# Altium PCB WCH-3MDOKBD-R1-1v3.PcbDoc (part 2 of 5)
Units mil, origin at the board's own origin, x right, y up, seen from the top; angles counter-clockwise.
Board outline 11710.74 x 4477.49 mil, 2 copper layers (Top Layer, Bottom Layer); 422 components, 246 nets, 927 pads, 1295 vias.
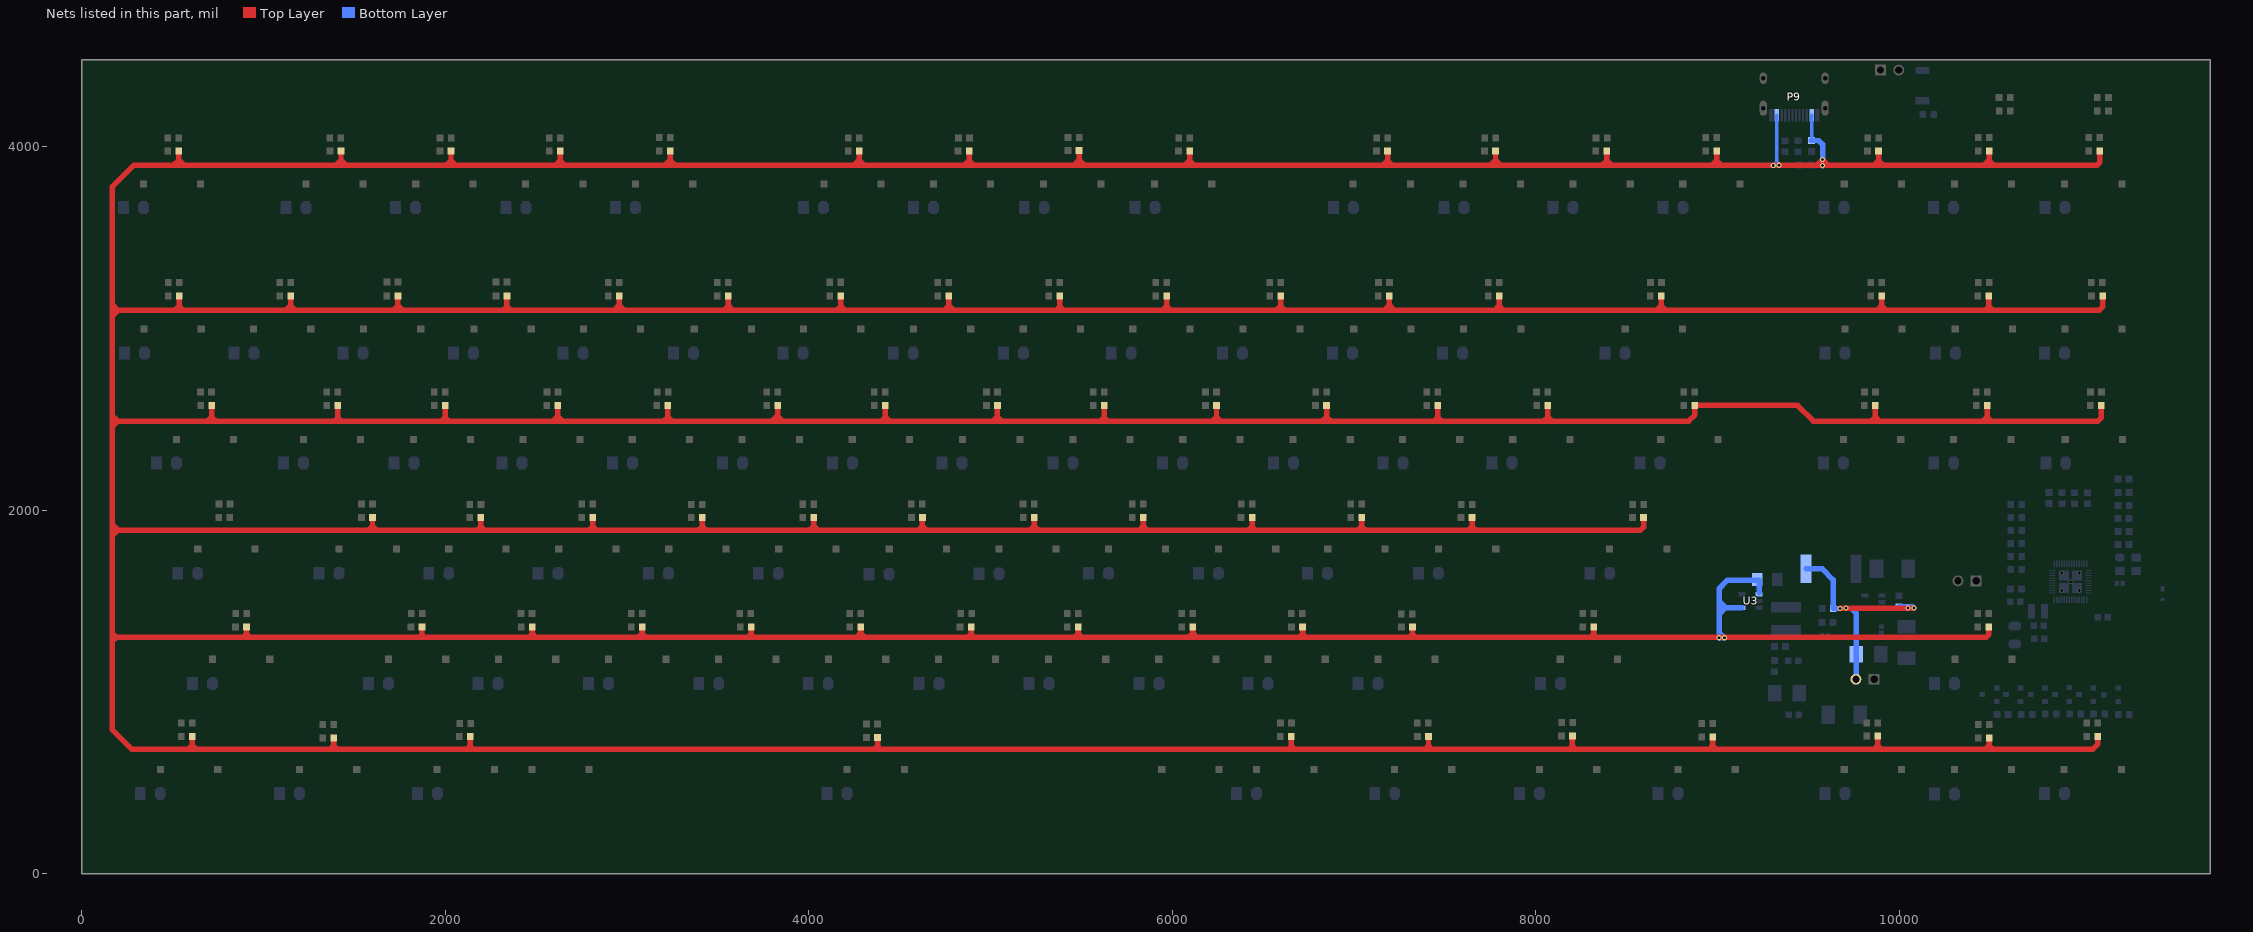
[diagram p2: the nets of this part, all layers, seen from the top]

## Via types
v1: diameter 28, hole 16, Top Layer to Bottom Layer, tented both sides, 1167 vias
v2: diameter 24, hole 12, Top Layer to Bottom Layer, tented both sides, 128 vias

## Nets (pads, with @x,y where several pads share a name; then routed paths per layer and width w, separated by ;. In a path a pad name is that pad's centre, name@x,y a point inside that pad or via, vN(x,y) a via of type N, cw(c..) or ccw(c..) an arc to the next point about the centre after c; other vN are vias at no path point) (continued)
+5V: C13.1 D199.A D227.A D228.A D229.A LD7.A LD8.A LD9.A LD10.A LD11.A LD12.A LD13.A LD14.A LD15.A LD16.A LD17.A LD18.A LD19.A LD21.A LD22.A LD23.A LD52.A LD53.A LD54.A LD55.A LD56.A LD57.A LD58.A LD59.A LD60.A LD61.A LD62.A LD63.A LD64.A LD65.A LD66.A LD67.A LD68.A LD93.A LD94.A LD95.A LD96.A LD97.A LD98.A LD99.A LD100.A LD101.A LD102.A LD103.A LD104.A LD105.A LD106.A LD107.A LD108.A LD109.A LD140.A LD141.A LD142.A LD143.A LD144.A LD145.A LD146.A LD147.A LD148.A LD149.A LD150.A LD151.A LD186.A LD187.A LD188.A LD189.A LD190.A LD191.A LD192.A LD193.A LD194.A LD195.A LD196.A LD197.A LD216.A LD217.A LD218.A LD219.A LD220.A LD223.A LD224.A LD_Fn.A P9.A4 P9.B4 R120.2 U3.1 U3.4 | length 79078.6
  Top Layer w30: 181.93,1299.88 191.02,1299.88 ; 535.31,3902.68 535.31,3926.41 ; LD7.A@535.31,3974.68 535.31,3926.41 ; 536.96,3103.97 536.96,3123.41 ; LD52.A@536.96,3178.04 536.96,3123.41 ; LD216.A@609.65,754.02 609.65,707.07 ; LD93.A@715.77,2575.56 715.77,2511.81 ; LD186.A@907.17,1355.98 907.17,1319.78 ; LD53.A@1149.98,3178.04 1149.98,3125.55 ; LD217.A@1386.96,745.9 1386.96,703.42 ; LD94.A@1409.4,2575.56 1409.4,2506.45 ; LD8.A@1427.03,3974.68 1427.03,3924.64 ; LD140.A@1600.46,1958.93 1600.46,1911.21 ; LD54.A@1740.36,3178.04 1740.36,3125.91 ; LD187.A@1872.66,1355.98 1872.66,1316.44 ; LD95.A@2000.22,2575.56 2000.22,2509.1 ; LD9.A@2032.19,3974.68 2032.19,3922.79 ; LD218.A@2137.51,752.89 2137.51,700.94 ; LD141.A@2196.21,1958.93 2196.21,1908.98 ; LD55.A@2340.06,3178.04 2340.06,3119.75 ; LD188.A@2479.54,1355.98 2479.54,1320.12 ; LD96.A@2619.91,2575.56 2619.91,2516.11 ; LD10.A@2632.59,3974.68 2632.59,3921.47 ; LD142.A@2812.52,1958.93 2812.52,1910.44 ; LD56.A@2957.21,3178.04 2957.21,3127.09 ; LD189.A@3083.53,1355.98 3083.53,1321.18 ; LD97.A@3225.26,2575.56 3225.26,2511.9 ; LD11.A@3237.89,3974.68 3237.89,3925.14 ; LD143.A@3415,1958.93 3415,1909.78 ; LD57.A@3558.21,3178.04 3558.21,3123.97 ; LD190.A@3683.34,1355.98 3683.34,1316.71 ; LD98.A@3829.13,2575.56 3829.13,2519.76 ; LD144.A@4028.25,1960.07 4028.25,1912.17 ; LD58.A@4176.71,3178.04 4176.71,3122.1 ; LD12.A@4277.28,3974.68 4277.28,3924.46 ; LD191.A@4285.49,1355.98 4285.49,1323.43 ; LD219.A@4378.55,749.84 4378.55,702.7 ; LD99.A@4421.3,2575.56 4421.3,2510.41 ; LD145.A@4625.6,1959.98 4625.6,1911.6 ; LD59.A@4770.9,3178.04 4770.9,3126.34 ; LD13.A@4882.15,3974.68 4882.15,3922.76 ; LD192.A@4893.21,1355.98 4893.21,1318.91 ; LD100.A@5038.34,2575.56 5038.34,2513.17 ; LD146.A@5240.62,1960.08 5240.62,1911.5 ; LD60.A@5381.34,3178.04 5381.34,3120.73 ; LD193.A@5483.57,1355.98 5483.57,1320.74 ; LD14.A@5487.13,3977.21 5487.13,3926.34 ; LD101.A@5625.34,2575.56 5625.34,2509.61 ; LD147.A@5840.25,1958.93 5840.25,1911.44 ; LD61.A@5969.32,3178.04 5969.32,3122.21 ; LD15.A@6095.17,3974.68 6095.17,3921.75 ; LD194.A@6112.64,1355.98 6112.64,1323.51 ; LD102.A@6243.24,2575.56 6243.24,2511.86 ; LD148.A@6439,1958.93 6439,1909.1 ; LD62.A@6596.2,3178.04 6596.2,3123.43 ; LD220.A@6654.88,754.78 6654.88,702.72 ; LD195.A@6716.61,1355.98 6716.61,1318.53 ; LD103.A@6848.51,2575.56 6848.51,2512.65 ; LD149.A@7041.77,1958.93 7041.77,1909.7 ; LD16.A@7184.25,3974.68 7184.25,3921.68 ; LD63.A@7194.09,3178.04 7194.09,3126.97 ; LD196.A@7321.33,1355.98 7321.33,1317.87 ; LD_Fn.A@7409.48,754.78 7409.48,703.67 ; LD104.A@7460.26,2575.56 7460.26,2509.99 ; LD150.A@7648.87,1958.93 7648.87,1910.06 ; LD17.A@7778.06,3974.68 7778.06,3924.89 ; LD64.A@7798.02,3178.04 7798.02,3123.86 ; LD105.A@8065.67,2575.56 8065.67,2512.12 ; LD223.A@8201.34,756.15 8201.34,702.08 ; LD197.A@8317.72,1355.98 8317.72,1316.77 ; LD18.A@8390.67,3974.68 8390.67,3924.07 ; LD151.A@8592.3,1958.93 8592.3,1906.47 8575.31,1889.47 7669.46,1889.47 ; LD65.A@8689.72,3178.04 8689.72,3125.05 ; LD224.A@8972.68,752.51 8972.68,704.21 ; LD19.A@8994.91,3974.68 8994.91,3923.38 ; LD107.A@9867.1,2575.56 9867.1,2513.04 ; D227.A@9879.88,757.01 9879.88,704.68 ; LD21.A@9885.21,3974.68 9885.21,3921.98 ; LD66.A@9902.59,3178.04 9902.59,3125.35 ; LD108.A@10482.92,2575.56 10482.92,2510.52 ; D199.A@10492.12,1355.98 10492.12,1315.53 10476.46,1299.88 9037.27,1299.88 8334.61,1299.88 ; LD67.A@10492.22,3178.04 10492.22,3119.95 ; D228.A@10493.21,746.83 10493.21,705.8 ; LD22.A@10493.96,3975.24 10493.96,3925.41 ; D229.A@11090.96,754.67 11090.96,711.8 11062.65,683.49 10515.52,683.49 ; LD23.A@11102.17,3976.13 11102.17,3912.35 11087.19,3897.37 10518.12,3897.37 ; LD109.A@11109.71,2575.56 11109.71,2506.83 11091.49,2488.61 10504.84,2488.61 ; LD68.A@11117.51,3178.04 11117.51,3117.93 11098.27,3098.7 10513.47,3098.7 ; 168.43,1277.29 168.43,1322.47 ; 168.43,1277.29 168.43,791.96 276.91,683.49 586.07,683.49 ; 168.43,1277.29 191.02,1299.88 ; 168.43,1322.47 191.02,1299.88 ; 168.43,1322.47 168.43,1856.95 ; 168.43,1856.95 168.43,1881.75 ; 168.43,1856.95 200.95,1889.47 ; 168.43,1881.75 168.43,1921.99 ; 168.43,1881.75 176.16,1889.47 200.95,1889.47 ; 168.43,1921.99 168.43,2457.91 ; 168.43,1921.99 200.95,1889.47 ; 168.43,2457.91 168.43,2488.61 ; 168.43,2457.91 199.13,2488.61 ; 168.43,2488.61 168.43,2519.31 ; 168.43,2488.61 199.13,2488.61 ; 168.43,2519.31 199.13,2488.61 ; 168.43,2519.31 168.43,3068.45 ; 168.43,3068.45 168.43,3098.18 ; 168.43,3068.45 170.3,3068.45 200.55,3098.7 ; 168.43,3098.18 168.43,3130.47 ; 168.43,3098.18 168.95,3098.7 200.55,3098.7 ; 168.43,3130.47 168.78,3130.47 200.55,3098.7 ; 168.43,3130.47 168.43,3778.04 287.77,3897.37 506.27,3897.37 ; 191.02,1299.88 887.26,1299.88 ; 199.13,2488.61 692.57,2488.61 ; 200.55,3098.7 512.25,3098.7 ; 200.95,1889.47 1578.72,1889.47 ; 506.27,3897.37 564.35,3897.37 ; 506.27,3897.37 535.31,3926.41 ; 512.25,3098.7 536.96,3123.41 ; 512.25,3098.7 561.67,3098.7 ; 535.31,3926.41 564.35,3897.37 ; 536.96,3123.41 561.67,3098.7 ; 561.67,3098.7 1123.12,3098.7 ; 564.35,3897.37 1399.75,3897.37 ; 586.07,683.49 603.09,683.49 ; 586.07,683.49 609.65,707.07 ; 603.09,683.49 631.15,683.49 ; 603.09,683.49 609.65,690.04 609.65,704.99 ; 609.65,704.99 631.15,683.49 ; 609.65,704.99 609.65,707.07 ; 631.15,683.49 1367.02,683.49 ; 692.57,2488.61 712.36,2488.61 ; 692.57,2488.61 715.77,2511.81 ; 712.36,2488.61 738.97,2488.61 ; 712.36,2488.61 715.77,2492.02 715.77,2511.81 ; 715.77,2511.81 738.97,2488.61 ; 738.97,2488.61 1391.56,2488.61 ; 887.26,1299.88 907.17,1299.88 ; 887.26,1299.88 907.17,1319.78 ; 907.17,1299.88 927.07,1299.88 ; 907.17,1299.88 907.17,1319.78 ; 907.17,1319.78 927.07,1299.88 ; 927.07,1299.88 1856.09,1299.88 ; 1123.12,3098.7 1148.27,3098.7 ; 1123.12,3098.7 1149.98,3125.55 ; 1148.27,3098.7 1176.83,3098.7 ; 1148.27,3098.7 1149.98,3100.41 1149.98,3125.55 ; 1149.98,3125.55 1176.83,3098.7 ; 1176.83,3098.7 1713.15,3098.7 ; 1367.02,683.49 1391.52,683.49 ; 1367.02,683.49 1386.96,703.42 ; 1386.96,703.42 1406.9,683.49 ; 1386.96,703.42 1386.96,688.05 1391.52,683.49 ; 1391.52,683.49 1406.9,683.49 ; 1391.56,2488.61 1414.88,2488.61 ; 1391.56,2488.61 1409.4,2506.45 ; 1399.75,3897.37 1422.01,3897.37 ; 1399.75,3897.37 1427.03,3924.64 ; 1406.9,683.49 2120.06,683.49 ; 1409.4,2506.45 1427.23,2488.61 ; 1409.4,2506.45 1409.4,2494.1 1414.88,2488.61 ; 1414.88,2488.61 1427.23,2488.61 ; 1422.01,3897.37 1454.3,3897.37 ; 1422.01,3897.37 1427.03,3902.38 1427.03,3924.64 ; 1427.03,3924.64 1454.3,3897.37 ; 1427.23,2488.61 1979.73,2488.61 ; 1454.3,3897.37 2006.86,3897.37 ; 1578.72,1889.47 1596.93,1889.47 ; 1578.72,1889.47 1600.46,1911.21 ; 1596.93,1889.47 1622.2,1889.47 ; 1596.93,1889.47 1600.46,1893.01 1600.46,1911.21 ; 1600.46,1911.21 1622.2,1889.47 ; 1622.2,1889.47 2176.7,1889.47 ; 1713.15,3098.7 1737.62,3098.7 ; 1713.15,3098.7 1740.36,3125.91 ; 1737.62,3098.7 1767.57,3098.7 ; 1737.62,3098.7 1740.36,3101.43 1740.36,3125.91 ; 1740.36,3125.91 1767.57,3098.7 ; 1767.57,3098.7 2319.01,3098.7 ; 1856.09,1299.88 1872.66,1299.88 ; 1856.09,1299.88 1872.66,1316.44 ; 1872.66,1299.88 1872.66,1316.44 ; 1872.66,1299.88 1889.22,1299.88 ; 1872.66,1316.44 1889.22,1299.88 ; 1889.22,1299.88 2459.29,1299.88 ; 1979.73,2488.61 2006.19,2488.61 ; 1979.73,2488.61 2000.22,2509.1 ; 2000.22,2509.1 2020.71,2488.61 ; 2000.22,2509.1 2000.22,2494.58 2006.19,2488.61 ; 2006.19,2488.61 2020.71,2488.61 ; 2006.86,3897.37 2034.12,3897.37 ; 2006.86,3897.37 2006.86,3897.46 2032.19,3922.79 ; 2020.71,2488.61 2592.41,2488.61 ; 2032.19,3922.79 2057.61,3897.37 ; 2032.19,3922.79 2032.19,3899.31 2034.12,3897.37 ; 2034.12,3897.37 2057.61,3897.37 ; 2057.61,3897.37 2608.49,3897.37 ; 2120.06,683.49 2138.87,683.49 ; 2120.06,683.49 2137.51,700.94 ; 2137.51,700.94 2137.51,684.85 2138.87,683.49 ; 2137.51,700.94 2154.97,683.49 ; 2138.87,683.49 2154.97,683.49 ; 2154.97,683.49 4359.34,683.49 ; 2176.7,1889.47 2196.73,1889.47 ; 2176.7,1889.47 2196.21,1908.98 ; 2196.21,1908.98 2215.72,1889.47 ; 2196.21,1908.98 2196.21,1889.99 2196.73,1889.47 ; 2196.73,1889.47 2215.72,1889.47 ; 2215.72,1889.47 2791.56,1889.47 ; 2319.01,3098.7 2342.08,3098.7 ; 2319.01,3098.7 2340.06,3119.75 ; 2340.06,3119.75 2361.12,3098.7 ; 2340.06,3119.75 2340.06,3100.71 2342.08,3098.7 ; 2342.08,3098.7 2361.12,3098.7 ; 2361.12,3098.7 2928.81,3098.7 ; 2459.29,1299.88 2479.54,1299.88 ; 2459.29,1299.88 2479.54,1320.12 ; 2479.54,1299.88 2499.78,1299.88 ; 2479.54,1299.88 2479.54,1320.12 ; 2479.54,1320.12 2499.78,1299.88 ; 2499.78,1299.88 3062.23,1299.88 ; 2592.41,2488.61 2621.74,2488.61 ; 2592.41,2488.61 2619.91,2516.11 ; 2608.49,3897.37 2626.13,3897.37 ; 2608.49,3897.37 2632.59,3921.47 ; 2619.91,2515.08 2646.38,2488.61 ; 2619.91,2515.08 2619.91,2490.44 2621.74,2488.61 ; 2619.91,2515.08 2619.91,2516.11 ; 2621.74,2488.61 2646.38,2488.61 ; 2626.13,3897.37 2656.68,3897.37 ; 2626.13,3897.37 2632.59,3903.82 2632.59,3921.47 ; 2632.59,3921.47 2656.68,3897.37 ; 2646.38,2488.61 3201.97,2488.61 ; 2656.68,3897.37 3210.12,3897.37 ; 2791.56,1889.47 2809.94,1889.47 ; 2791.56,1889.47 2812.52,1910.44 ; 2809.94,1889.47 2831.71,1889.47 ; 2809.94,1889.47 2812.52,1892.06 2812.52,1908.66 ; 2812.52,1908.66 2831.71,1889.47 ; 2812.52,1908.66 2812.52,1910.44 ; 2831.71,1889.47 3394.7,1889.47 ; 2928.81,3098.7 2957.47,3098.7 ; 2928.81,3098.7 2957.21,3127.09 ; 2957.21,3127.09 2957.21,3098.96 2957.47,3098.7 ; 2957.21,3127.09 2985.6,3098.7 ; 2957.47,3098.7 2985.6,3098.7 ; 2985.6,3098.7 3532.93,3098.7 ; 3062.23,1299.88 3083.53,1299.88 ; 3062.23,1299.88 3083.53,1321.18 ; 3083.53,1299.88 3083.53,1321.18 ; 3083.53,1299.88 3104.84,1299.88 ; 3083.53,1321.18 3104.84,1299.88 ; 3104.84,1299.88 3666.51,1299.88 ; 3201.97,2488.61 3231.41,2488.61 ; 3201.97,2488.61 3225.26,2511.9 ; 3210.12,3897.37 3237.89,3925.14 ; 3210.12,3897.37 3239.14,3897.37 ; 3225.26,2511.9 3248.55,2488.61 ; 3225.26,2511.9 3225.26,2494.77 3231.41,2488.61 ; 3231.41,2488.61 3248.55,2488.61 ; 3237.89,3925.14 3237.89,3898.62 3239.14,3897.37 ; 3237.89,3925.14 3265.65,3897.37 ; 3239.14,3897.37 3265.65,3897.37 ; 3248.55,2488.61 3797.99,2488.61 ; 3265.65,3897.37 4250.19,3897.37 ; 3394.7,1889.47 3418.08,1889.47 ; 3394.7,1889.47 3415,1909.78 ; 3415,1908.71 3434.24,1889.47 ; 3415,1908.71 3415,1892.55 3418.08,1889.47 ; 3415,1908.71 3415,1909.78 ; 3418.08,1889.47 3434.24,1889.47 ; 3434.24,1889.47 4005.56,1889.47 ; 3532.93,3098.7 3556.05,3098.7 ; 3532.93,3098.7 3558.21,3123.97 ; 3556.05,3098.7 3583.48,3098.7 ; 3556.05,3098.7 3558.21,3100.85 3558.21,3123.97 ; 3558.21,3123.97 3583.48,3098.7 ; 3583.48,3098.7 4153.31,3098.7 ; 3666.51,1299.88 3683.34,1299.88 ; 3666.51,1299.88 3683.34,1316.71 ; 3683.34,1299.88 3683.34,1316.71 ; 3683.34,1299.88 3700.17,1299.88 ; 3683.34,1316.71 3700.17,1299.88 ; 3700.17,1299.88 4261.94,1299.88 ; 3797.99,2488.61 3827.86,2488.61 ; 3797.99,2488.61 3829.13,2519.76 ; 3827.86,2488.61 3856.57,2488.61 ; 3827.86,2488.61 3829.13,2489.88 3829.13,2516.04 ; 3829.13,2516.04 3856.57,2488.61 ; 3829.13,2516.04 3829.13,2519.76 ; 3856.57,2488.61 4399.5,2488.61 ; 4005.56,1889.47 4028.01,1889.47 ; 4005.56,1889.47 4028.25,1912.17 ; 4028.01,1889.47 4028.25,1889.72 4028.25,1912.17 ; 4028.01,1889.47 4050.95,1889.47 ; 4028.25,1912.17 4050.95,1889.47 ; 4050.95,1889.47 4603.48,1889.47 ; 4153.31,3098.7 4175.65,3098.7 ; 4153.31,3098.7 4176.71,3122.1 ; 4175.65,3098.7 4200.1,3098.7 ; 4175.65,3098.7 4176.71,3099.76 4176.71,3122.1 ; 4176.71,3122.1 4200.1,3098.7 ; 4200.1,3098.7 4743.26,3098.7 ; 4250.19,3897.37 4277.99,3897.37 ; 4250.19,3897.37 4277.28,3924.46 ; 4261.94,1299.88 4285.49,1299.88 ; 4261.94,1299.88 4285.49,1323.43 ; 4277.28,3924.46 4304.37,3897.37 ; 4277.28,3924.46 4277.28,3898.07 4277.99,3897.37 ; 4277.99,3897.37 4304.37,3897.37 ; 4285.49,1299.88 4309.04,1299.88 ; 4285.49,1299.88 4285.49,1323.43 ; 4285.49,1323.43 4309.04,1299.88 ; 4304.37,3897.37 4856.76,3897.37 ; 4309.04,1299.88 4874.17,1299.88 ; 4359.34,683.49 4375.7,683.49 ; 4359.34,683.49 4378.55,702.7 ; 4375.7,683.49 4397.76,683.49 ; 4375.7,683.49 4378.55,686.34 4378.55,702.7 ; 4378.55,702.7 4397.76,683.49 ; 4397.76,683.49 6635.65,683.49 ; 4399.5,2488.61 4421.3,2510.41 ; 4399.5,2488.61 4425,2488.61 ; 4421.3,2510.41 4443.1,2488.61 ; 4421.3,2510.41 4421.3,2492.31 4425,2488.61 ; 4425,2488.61 4443.1,2488.61 ; 4443.1,2488.61 5013.78,2488.61 ; 4603.48,1889.47 4628.23,1889.47 ; 4603.48,1889.47 4625.6,1911.6 ; 4625.6,1910.78 4646.92,1889.47 ; 4625.6,1910.78 4625.6,1892.1 4628.23,1889.47 ; 4625.6,1910.78 4625.6,1911.6 ; 4628.23,1889.47 4646.92,1889.47 ; 4646.92,1889.47 5218.59,1889.47 ; 4743.26,3098.7 4770.84,3098.7 ; 4743.26,3098.7 4770.9,3126.34 ; 4770.84,3098.7 4796.37,3098.7 ; 4770.84,3098.7 4770.9,3098.76 4770.9,3126.34 ; 4770.9,3126.34 4796.37,3100.88 4796.37,3098.7 ; 4796.37,3098.7 5359.31,3098.7 ; 4856.76,3897.37 4882.15,3922.76 ; 4856.76,3897.37 4890.17,3897.37 ; 4874.17,1299.88 4893.21,1299.88 ; 4874.17,1299.88 4893.21,1318.91 ; 4882.15,3922.76 4907.54,3897.37 ; 4882.15,3922.76 4882.15,3905.38 4890.17,3897.37 ; 4890.17,3897.37 4907.54,3897.37 ; 4893.21,1299.88 4893.21,1318.91 ; 4893.21,1299.88 4912.25,1299.88 ; 4893.21,1318.91 4912.25,1299.88 ; 4907.54,3897.37 5458.16,3897.37 ; 4912.25,1299.88 5462.71,1299.88 ; 5013.78,2488.61 5038.34,2513.17 ; 5013.78,2488.61 5038.71,2488.61 ; 5038.34,2512.7 5038.34,2488.98 5038.71,2488.61 ; 5038.34,2512.7 5062.43,2488.61 ; 5038.34,2512.7 5038.34,2513.17 ; 5038.71,2488.61 5062.43,2488.61 ; 5062.43,2488.61 5604.34,2488.61 ; 5218.59,1889.47 5241.19,1889.47 ; 5218.59,1889.47 5240.62,1911.5 ; 5240.62,1911.5 5262.65,1889.47 ; 5240.62,1911.5 5240.62,1890.04 5241.19,1889.47 ; 5241.19,1889.47 5262.65,1889.47 ; 5262.65,1889.47 5818.28,1889.47 ; 5359.31,3098.7 5382.63,3098.7 ; 5359.31,3098.7 5381.34,3120.73 ; 5381.34,3118.84 5401.48,3098.7 ; 5381.34,3118.84 5381.34,3120.73 ; 5381.34,3118.84 5381.34,3099.98 5382.63,3098.7 ; 5382.63,3098.7 5401.48,3098.7 ; 5401.48,3098.7 5945.8,3098.7 ; 5458.16,3897.37 5487.13,3926.34 ; 5458.16,3897.37 5492.27,3897.37 ; 5462.71,1299.88 5483.57,1299.88 ; 5462.71,1299.88 5483.57,1320.74 ; 5483.57,1299.88 5483.57,1320.74 ; 5483.57,1299.88 5504.43,1299.88 ; 5483.57,1320.74 5504.43,1299.88 ; 5487.13,3926.34 5516.1,3897.37 ; 5487.13,3926.34 5487.13,3902.5 5492.27,3897.37 ; 5492.27,3897.37 5516.1,3897.37 ; 5504.43,1299.88 6089.57,1299.88 ; 5516.1,3897.37 6070.79,3897.37 ; 5604.34,2488.61 5625.78,2488.61 ; 5604.34,2488.61 5625.34,2509.61 ; 5625.34,2509.11 5645.83,2488.61 ; 5625.34,2509.11 5625.34,2489.06 5625.78,2488.61 ; 5625.34,2509.11 5625.34,2509.61 ; 5625.78,2488.61 5645.83,2488.61 ; 5645.83,2488.61 6219.98,2488.61 ; 5818.28,1889.47 5844.25,1889.47 ; 5818.28,1889.47 5840.25,1911.44 ; 5840.25,1911.21 5840.25,1893.47 5844.25,1889.47 ; 5840.25,1911.21 5861.99,1889.47 ; 5840.25,1911.21 5840.25,1911.44 ; 5844.25,1889.47 5861.99,1889.47 ; 5861.99,1889.47 6419.38,1889.47 ; 5945.8,3098.7 5972.6,3098.7 ; 5945.8,3098.7 5969.32,3122.21 ; 5969.32,3122.21 5992.83,3098.7 ; 5969.32,3122.21 5969.32,3101.98 5972.6,3098.7 ; 5972.6,3098.7 5992.83,3098.7 ; 5992.83,3098.7 6575.08,3098.7 ; 6070.79,3897.37 6095.17,3921.75 ; 6070.79,3897.37 6088.78,3897.37 ; 6088.78,3897.37 6119.54,3897.37 ; 6088.78,3897.37 6095.17,3903.75 6095.17,3921.75 ; 6089.57,1299.88 6112.64,1299.88 ; 6089.57,1299.88 6089.57,1300.44 6112.64,1323.51 ; 6095.17,3921.75 6119.54,3897.37 ; 6112.64,1299.88 6112.64,1323.51 ; 6112.64,1299.88 6136.27,1299.88 ; 6112.64,1323.51 6136.27,1299.88 ; 6119.54,3897.37 7159.93,3897.37 ; 6136.27,1299.88 6697.96,1299.88 ; 6219.98,2488.61 6243.43,2488.61 ; 6219.98,2488.61 6243.24,2511.86 ; 6243.24,2511.62 6266.24,2488.61 ; 6243.24,2511.62 6243.24,2488.8 6243.43,2488.61 ; 6243.24,2511.62 6243.24,2511.86 ; 6243.43,2488.61 6266.24,2488.61 ; 6266.24,2488.61 6824.47,2488.61 ; 6419.38,1889.47 6440.71,1889.47 ; 6419.38,1889.47 6439,1909.1 ; 6439,1909.1 6458.62,1889.47 ; 6439,1909.1 6439,1891.19 6440.71,1889.47 ; 6440.71,1889.47 6458.62,1889.47 ; 6458.62,1889.47 7021.55,1889.47 ; 6575.08,3098.7 6597.81,3098.7 ; 6575.08,3098.7 6575.08,3102.32 6596.2,3123.43 ; 6596.2,3123.43 6620.93,3098.7 ; 6596.2,3123.43 6596.2,3100.32 6597.81,3098.7 ; 6597.81,3098.7 6620.93,3098.7 ; 6620.93,3098.7 7165.81,3098.7 ; 6635.65,683.49 6658.51,683.49 ; 6635.65,683.49 6654.88,702.72 ; 6654.88,702.72 6674.11,683.49 ; 6654.88,702.72 6654.88,687.11 6658.51,683.49 ; 6658.51,683.49 6674.11,683.49 ; 6674.11,683.49 7389.29,683.49 ; 6697.96,1299.88 6716.61,1299.88 ; 6697.96,1299.88 6716.61,1318.53 ; 6716.61,1299.88 6716.61,1318.53 ; 6716.61,1299.88 6735.26,1299.88 ; 6716.61,1318.53 6735.26,1299.88 ; 6735.26,1299.88 7303.34,1299.88 ; 6824.47,2488.61 6848.51,2512.65 ; 6824.47,2488.61 6851.46,2488.61 ; 6848.51,2512.65 6872.54,2488.61 ; 6848.51,2512.65 6848.51,2491.56 6851.46,2488.61 ; 6851.46,2488.61 6872.54,2488.61 ; 6872.54,2488.61 7438.88,2488.61 ; 7021.55,1889.47 7047.72,1889.47 ; 7021.55,1889.47 7041.77,1909.7 ; 7041.77,1909.7 7041.77,1895.42 7047.72,1889.47 ; 7041.77,1909.7 7061.99,1889.47 ; 7047.72,1889.47 7061.99,1889.47 ; 7061.99,1889.47 7628.29,1889.47 ; 7159.93,3897.37 7184.73,3897.37 ; 7159.93,3897.37 7184.25,3921.68 ; 7165.81,3098.7 7194.09,3126.97 ; 7165.81,3098.7 7199.24,3098.7 ; 7184.25,3921.68 7208.56,3897.37 ; 7184.25,3921.68 7184.25,3897.85 7184.73,3897.37 ; 7184.73,3897.37 7208.56,3897.37 ; 7194.09,3126.97 7194.09,3103.84 7199.24,3098.7 ; 7194.09,3126.97 7220.73,3100.34 7220.73,3098.7 ; 7199.24,3098.7 7220.73,3098.7 ; 7208.56,3897.37 7750.54,3897.37 ; 7220.73,3098.7 7772.85,3098.7 ; 7303.34,1299.88 7321.33,1299.88 ; 7303.34,1299.88 7321.33,1317.87 ; 7321.33,1299.88 7321.33,1317.87 ; 7321.33,1299.88 7339.33,1299.88 ; 7321.33,1317.87 7339.33,1299.88 ; 7339.33,1299.88 8300.82,1299.88 ; 7389.29,683.49 7407.66,683.49 ; 7389.29,683.49 7409.48,703.67 ; 7407.66,683.49 7429.66,683.49 ; 7407.66,683.49 7409.48,685.3 7409.48,703.67 ; 7409.48,703.67 7429.66,683.49 ; 7429.66,683.49 8182.76,683.49 ; 7438.88,2488.61 7463.86,2488.61 ; 7438.88,2488.61 7460.26,2509.99 ; 7460.26,2509.99 7481.64,2488.61 ; 7460.26,2509.99 7460.26,2492.21 7463.86,2488.61 ; 7463.86,2488.61 7481.64,2488.61 ; 7481.64,2488.61 8042.16,2488.61 ; 7628.29,1889.47 7651.94,1889.47 ; 7628.29,1889.47 7648.87,1910.06 ; 7648.87,1910.06 7648.87,1892.54 7651.94,1889.47 ; 7648.87,1910.06 7669.46,1889.47 ; 7651.94,1889.47 7669.46,1889.47 ; 7750.54,3897.37 7778.42,3897.37 ; 7750.54,3897.37 7778.06,3924.89 ; 7772.85,3098.7 7798.24,3098.7 ; 7772.85,3098.7 7798.02,3123.86 ; 7778.06,3924.89 7805.57,3897.37 ; 7778.06,3924.89 7778.06,3897.74 7778.42,3897.37 ; 7778.42,3897.37 7805.57,3897.37 ; 7798.02,3123.86 7798.02,3098.92 7798.24,3098.7 ; 7798.02,3123.86 7823.19,3098.7 ; 7798.24,3098.7 7823.19,3098.7 ; 7805.57,3897.37 8363.96,3897.37 ; 7823.19,3098.7 8663.36,3098.7 ; 8042.16,2488.61 8060.54,2488.61 ; 8042.16,2488.61 8065.67,2512.12 ; 8060.54,2488.61 8089.17,2488.61 ; 8060.54,2488.61 8065.67,2493.74 8065.67,2512.12 ; 8065.67,2512.12 8089.17,2488.61 ; 8089.17,2488.61 8840.24,2488.61 8874.55,2522.92 LD106.A@8874.55,2575.56 9439.92,2575.56 9526.87,2488.61 9842.67,2488.61 ; 8182.76,683.49 8202.19,683.49 ; 8182.76,683.49 8201.34,702.08 ; 8201.34,702.08 8219.93,683.49 ; 8201.34,702.08 8201.34,684.34 8202.19,683.49 ; 8202.19,683.49 8219.93,683.49 ; 8219.93,683.49 8951.97,683.49 ; 8300.82,1299.88 8317.72,1299.88 ; 8300.82,1299.88 8317.72,1316.77 ; 8317.72,1299.88 8334.61,1299.88 ; 8317.72,1299.88 8317.72,1316.77 ; 8317.72,1316.77 8334.61,1299.88 ; 8363.96,3897.37 8390.67,3924.07 ; 8363.96,3897.37 8391.21,3897.37 ; 8390.67,3924.07 8417.37,3897.37 ; 8390.67,3924.07 8390.67,3897.91 8391.21,3897.37 ; 8391.21,3897.37 8417.37,3897.37 ; 8417.37,3897.37 8969.76,3897.37 ; 8663.36,3098.7 8689.72,3125.05 ; 8663.36,3098.7 8693.78,3098.7 ; 8689.72,3125.05 8689.72,3102.76 8693.78,3098.7 ; 8689.72,3125.05 8716.07,3098.7 ; 8693.78,3098.7 8716.07,3098.7 ; 8716.07,3098.7 9875.93,3098.7 ; 8951.97,683.49 8971.36,683.49 ; 8951.97,683.49 8972.68,704.21 ; 8969.76,3897.37 8969.76,3898.23 8994.91,3923.38 ; 8969.76,3897.37 9001.19,3897.37 ; 8971.36,683.49 8993.4,683.49 ; 8971.36,683.49 8972.68,684.81 8972.68,704.21 ; 8972.68,704.21 8993.4,683.49 ; 8993.4,683.49 9858.69,683.49 ; 8994.91,3923.38 8994.91,3903.65 9001.19,3897.37 ; 8994.91,3923.38 9020.92,3897.37 ; 9001.19,3897.37 9020.92,3897.37 ; 9020.92,3897.37 9546.22,3897.37 ; 9546.22,3897.37 v1(9576.14,3927.29) ; 9546.22,3897.37 v1@9577.53,3897.37 ; v1(9576.14,3927.29) 9606.07,3897.37 ; v1(9576.14,3927.29) 9576.14,3898.75 v1@9577.53,3897.37 ; v1@9577.53,3897.37 9606.07,3897.37 ; 9606.07,3897.37 9621.09,3897.37 9862.81,3897.37 ; 9842.67,2488.61 9867.1,2513.04 ; 9842.67,2488.61 9874.16,2488.61 ; 9858.69,683.49 9881.55,683.49 ; 9858.69,683.49 9879.88,704.68 ; 9862.81,3897.37 9881,3897.37 ; 9862.81,3897.37 9862.81,3899.58 9885.21,3921.98 ; 9867.1,2512.73 9867.1,2495.67 9874.16,2488.61 ; 9867.1,2512.73 9891.22,2488.61 ; 9867.1,2512.73 9867.1,2513.04 ; 9874.16,2488.61 9891.22,2488.61 ; 9875.93,3098.7 9900.62,3098.7 ; 9875.93,3098.7 9902.59,3125.35 ; 9879.88,704.68 9901.07,683.49 ; 9879.88,704.68 9879.88,685.16 9881.55,683.49 ; 9881,3897.37 9909.81,3897.37 ; 9881,3897.37 9885.21,3901.58 9885.21,3921.98 ; 9881.55,683.49 9901.07,683.49 ; 9885.21,3921.98 9909.81,3897.37 ; 9891.22,2488.61 10461.01,2488.61 ; 9900.62,3098.7 9929.24,3098.7 ; 9900.62,3098.7 9902.59,3100.67 9902.59,3125.35 ; 9901.07,683.49 10470.9,683.49 ; 9902.59,3125.35 9929.24,3098.7 ; 9909.81,3897.37 10465.92,3897.37 ; 9929.24,3098.7 10470.97,3098.7 ; 10461.01,2488.61 10485.62,2488.61 ; 10461.01,2488.61 10482.92,2510.52 ; 10465.92,3897.37 10493.22,3897.37 ; 10465.92,3897.37 10493.96,3925.41 ; 10470.9,683.49 10489.3,683.49 ; 10470.9,683.49 10493.21,705.8 ; 10470.97,3098.7 10492.27,3098.7 ; 10470.97,3098.7 10492.22,3119.95 ; 10482.92,2510.52 10504.84,2488.61 ; 10482.92,2510.52 10482.92,2491.31 10485.62,2488.61 ; 10485.62,2488.61 10504.84,2488.61 ; 10489.3,683.49 10515.52,683.49 ; 10489.3,683.49 10493.21,687.4 10493.21,705.8 ; 10492.22,3119.95 10492.22,3098.75 10492.27,3098.7 ; 10492.22,3119.95 10513.47,3098.7 ; 10492.27,3098.7 10513.47,3098.7 ; 10493.21,705.8 10515.52,683.49 ; 10493.22,3897.37 10518.12,3897.37 ; 10493.22,3897.37 10493.96,3898.11 10493.96,3921.53 ; 10493.96,3921.53 10518.12,3897.37 ; 10493.96,3921.53 10493.96,3925.41
  Bottom Layer w20: P9.A4@9324.77,4172.15 9324.77,3914.85 ; R120.2@9515.84,4032.83 9517.68,4034.67 P9.B4@9517.68,4172.15 ; 9324.77,3914.85 v1(9305.76,3895.85) 9335.62,3895.85 v1(9336.41,3896.64) 9336.41,3903.2 9324.77,3914.85
  Bottom Layer w30: U3.4@9133.76,1462.65 9043.85,1462.65 ; U3.1@9228.25,1544.25 9228.25,1613.18 9226.88,1614.55 9055.24,1614.55 9007.66,1566.98 9007.66,1498.83 ; R120.2@9515.84,4032.83 9555.71,4032.83 9577.53,4011.01 v1(9577.53,3894.97) ; 9007.66,1326.96 v1(9037.27,1297.35) 9007.97,1297.35 v1(9007.66,1297.66) 9007.66,1326.96 ; 9007.66,1326.96 9007.66,1427.79 ; 9007.66,1427.79 9007.66,1460.87 ; 9007.66,1427.79 9009,1427.79 9043.85,1462.65 ; 9007.66,1460.87 9007.66,1498.83 ; 9007.66,1460.87 9009.44,1462.65 9043.85,1462.65 ; 9007.66,1498.83 9043.85,1462.65
BT+: C2.2 J1.2 L1.1 R117.2 R121.2 | length 1409.8
  Top Layer w30: v1(9674.11,1459.15) 9675.44,1460.48 v1(9706.68,1460.48) v1(10079.14,1460.48)
  Bottom Layer w30: L1.1@9486.01,1676.23 9575.78,1676.23 9635.57,1616.44 R121.2@9635.57,1458.22 9736.37,1458.22 9763.17,1431.43 C2.2@9763.17,1206.15 9763.17,1071.53 J1.2@9760.69,1069.05 ; R117.2@9997.61,1468.31 10071.31,1468.31 v1(10079.14,1460.48) 10005.45,1460.48 R117.2@9997.61,1468.31
  other v1: 10047.81,1460.77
